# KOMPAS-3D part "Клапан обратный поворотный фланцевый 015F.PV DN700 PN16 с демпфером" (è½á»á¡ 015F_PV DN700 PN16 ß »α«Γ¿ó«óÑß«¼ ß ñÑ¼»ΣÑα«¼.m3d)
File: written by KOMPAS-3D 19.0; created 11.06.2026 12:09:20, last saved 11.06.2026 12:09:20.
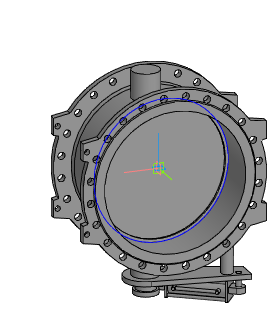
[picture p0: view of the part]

Document properties: Автор: Энергия; Полное имя файла: Z:\3.Личные\kachalov\001_3d для проектировщиков\5.5 Тип 015F.PV Клапан обратный поворотный с двумя эксцентриками\_stp_Клапан 015F.PV DN300-DN1200 с противовесом с демпфером\Клапан 015F_PV DN700 PN16 с противовесом с демпфером.m3d

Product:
- Part/product: Клапан обратный поворотный фланцевый 015F.PV DN700 PN16 с демпфером

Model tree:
1. Операция без истории:1
2. Сплайн:1
     Координата Y = 30; Координата Z = 350; Вес = 1; Координата X = 700; Координата Y = 122.157; Координата Z = 350; Вес = 0.333333; Координата X = 700; Координата Y = 122.157; Координата Z = -350; Вес = 0.333333; Координата Y = 30; Координата Z = -350; Вес = 1; Координата X = -700; Координата Y = -62.1567; Координата Z = -350; Вес = 0.333333; Координата X = -700; Координата Y = -62.1567; Координата Z = 350; Вес = 0.333333; Порядок = 4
